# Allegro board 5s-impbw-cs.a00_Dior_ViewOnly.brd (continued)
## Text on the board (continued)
GND2: list("[Spacing] GND2" "Shape to Thru Via" "6 MIL [DEFAULT]" "5.99 MIL" "0.01 MIL" "DRC ERROR CLASS/GND2" "[ThruVia] USB3_TX_P2_OUT (VIA20D10A32) (9985.5 -6273.0)" "[Gnd2 Shape] GND ((9771.94 -9313.68) (17202.26 -5741.63))" list(9976.030000 -6269.780000) nil)@@@list("liquid_ni" "2014/02/18 09:27:21" nil "s0dcoa16607a" "5s-impbw-cs.104")@@@list("jake_ma" "2014/02/18 09:40:55" nil "s0dcoa89107" "5s-impbw-cs.104") | list("[Spacing] GND2" "Shape to Thru Via" "6 MIL [DEFAULT]" "5.99 MIL" "0.01 MIL" "DRC ERROR CLASS/GND2" "[ThruVia] USB3_RX_N3_OUT (VIA20D10A32) (9979.0 -6248.0)" "[Gnd2 Shape] GND ((9771.94 -9313.68) (17202.26 -5741.63))" list(9986.740000 -6254.330000) nil)@@@list("liquid_ni" "2014/02/18 09:27:20" nil "s0dcoa16607a" "5s-impbw-cs.104")@@@list("jake_ma" "2014/02/18 09:40:52" nil "s0dcoa89107" "5s-impbw-cs.104") | list("[Spacing] GND2" "Shape to Thru Via" "6 MIL [DEFAULT]" "5.99 MIL" "0.01 MIL" "DRC ERROR CLASS/GND2" "[ThruVia] USB3_TX_N2_OUT (TPCT30B20D10_SS16) (9995.0 -6302.5)" "[Gnd2 Shape] GND ((9771.94 -9313.68) (17202.26 -5741.63))" list(10004.520000 -6299.430000) nil)@@@list("liquid_ni" "2014/02/18 09:27:20" nil "s0dcoa16607a" "5s-impbw-cs.104")@@@list("jake_ma" "2014/02/18 09:40:53" nil "s0dcoa89107" "5s-impbw-cs.104") | list("[Spacing] GND2" "Shape to Thru Via" "6 MIL [DEFAULT]" "5.99 MIL" "0.01 MIL" "DRC ERROR CLASS/GND2" "[ThruVia] SATA_TXN1 (VIA20D10A32) (10481.51 -7037.77)" "[Gnd2 Shape] GND ((9771.94 -9313.68) (17202.26 -5741.63))" list(10490.660000 -7033.740000) nil)@@@list("liquid_ni" "2014/02/18 09:27:19" nil "s0dcoa16607a" "5s-impbw-cs.104")@@@list("jake_ma" "2014/02/18 09:40:50" nil "s0dcoa89107" "5s-impbw-cs.104") | list("[Spacing] GND2" "Shape to Thru Via" "6 MIL [DEFAULT]" "5.99 MIL" "0.01 MIL" "DRC ERROR CLASS/GND2" "[ThruVia] SATA_TXP0 (VIA20D10A32) (10510.6 -7038.2)" "[Gnd2 Shape] GND ((9771.94 -9313.68) (17202.26 -5741.63))" list(10501.450000 -7042.230000) nil)@@@list("liquid_ni" "2014/02/18 09:27:19" nil "s0dcoa16607a" "5s-impbw-cs.104")@@@list("jake_ma" "2014/02/18 09:40:51" nil "s0dcoa89107" "5s-impbw-cs.104") | list("[Spacing] GND2" "Thru Via to Thru Via" "5 MIL [(20)]" "4.24 MIL" "0.76 MIL" "DRC ERROR CLASS/GND2" "[ThruVia] SATA_TXP0 (VIA20D10A32) (10510.6 -7038.2)" "[ThruVia] SATA_TXN0 (VIA20D10A32) (10534.83 -7037.68)" list(10520.600000 -7037.990000) nil)@@@list("liquid_ni" "2014/02/18 09:27:24" nil "s0dcoa16607a" "5s-impbw-cs.104")@@@list("jake_ma" "2014/02/18 10:19:29" nil "S0DCOA89107" "5s-impbw-cs.104") | list("[Spacing] GND2" "1.Thru Via to Thru Via" "5 MIL [(20)]" "4.49 MIL" "0.51 MIL" "DRC ERROR CLASS/GND2" "[ThruVia] SATA_RXP0 (VIA20D10A32) (10722.16 -6789.07)" "[ThruVia] SATA_RXN0 (VIA20D10A32) (10746.63 -6790.03)" list(10732.150000 -6789.460000) nil)@@@list("liquid_ni" "2014/02/18 09:27:25" nil "s0dcoa16607a" "5s-impbw-cs.104")@@@list("jake_ma" "2014/02/18 10:27:57" nil "S0DCOA89107" "5s-impbw-cs.104") | list("[Spacing] GND2" "Shape to Route Keepout" "0 MIL [DEFAULT]" "0 MIL" "0.00 MIL" "DRC ERROR CLASS/GND2" "[Shape] Route Keepout/All ((12207.38 -8787.48) (12294.0 -8700.86))" "[Gnd2 Shape] GND ((9771.94 -9313.68) (17202.26 -5741.63))" list(12207.380000 -8744.170000) nil)@@@list("liquid_ni" "2014/02/18 09:27:21" nil "s0dcoa16607a" "5s-impbw-cs.104")@@@list("jake_ma" "2014/02/18 09:40:56" nil "s0dcoa89107" "5s-impbw-cs.104") | list("[Spacing] GND2" "Shape to Route Keepout" "0 MIL [DEFAULT]" "0 MIL" "0.00 MIL" "DRC ERROR CLASS/GND2" "[Shape] Route Keepout/All ((13694.97 -8866.99) (13781.59 -8780.37))" "[Gnd2 Shape] GND ((9771.94 -9313.68) (17202.26 -5741.63))" list(13781.590000 -8823.680000) nil)@@@list("liquid_ni" "2014/02/18 09:27:22" nil "s0dcoa16607a" "5s-impbw-cs.104")@@@list("jake_ma" "2014/02/18 09:40:58" nil "s0dcoa89107" "5s-impbw-cs.104") | list("[Spacing] GND2" "Shape to Route Keepout" "0 MIL [DEFAULT]" "0 MIL" "0.00 MIL" "DRC ERROR CLASS/GND2" "[Shape] Route Keepout/All ((16620.24 -7753.74) (16686.86 -7687.12))" "[Gnd2 Shape] GND ((9771.94 -9313.68) (17202.26 -5741.63))" list(16686.860000 -7720.430000) nil)@@@list("liquid_ni" "2014/02/18 09:27:22" nil "s0dcoa16607a" "5s-impbw-cs.104")@@@list("jake_ma" "2014/02/18 09:40:59" nil "s0dcoa89107" "5s-impbw-cs.104") | list("[Spacing] GND2" "Shape to Route Keepout" "0 MIL [DEFAULT]" "0 MIL" "0.00 MIL" "DRC ERROR CLASS/GND2" "[Shape] Route Keepout/All ((17114.81 -7812.93) (17207.43 -7720.31))" "[Gnd2 Shape] GND ((9771.94 -9313.68) (17202.26 -5741.63))" list(17115.610000 -7775.180000) nil)@@@list("liquid_ni" "2014/02/18 09:27:23" nil "s0dcoa16607a" "5s-impbw-cs.104")@@@list("jake_ma" "2014/02/18 09:41:00" nil "s0dcoa89107" "5s-impbw-cs.104") | list("[Spacing] GND2" "Shape to Route Keepout" "0 MIL [DEFAULT]" "0 MIL" "0.00 MIL" "DRC ERROR CLASS/GND2" "[Shape] Route Keepout/All ((17114.81 -6506.23) (17207.43 -6413.61))" "[Gnd2 Shape] GND ((9771.94 -9313.68) (17202.26 -5741.63))" list(17198.170000 -6432.140000) nil)@@@list("liquid_ni" "2014/02/18 09:27:23" nil "s0dcoa16607a" "5s-impbw-cs.104")@@@list("jake_ma" "2014/02/18 09:41:02" nil "s0dcoa89107" "5s-impbw-cs.104") | list("[Spacing] GND2" "Shape to Route Keepin" "0 MIL [DEFAULT]" "0 MIL" "0.00 MIL" "DRC ERROR CLASS/GND2" "[Shape] Route Keepin/All ((9771.94 -9313.68) (17202.26 -5741.63))" "[Gnd2 Shape] GND ((9771.94 -9313.68) (17202.26 -5741.63))" list(17202.260000 -6481.190000) nil)@@@list("liquid_ni" "2014/02/18 09:27:24" nil "s0dcoa16607a" "5s-impbw-cs.104")@@@list("jake_ma" "2014/02/18 09:41:03" nil "s0dcoa89107" "5s-impbw-cs.104")
User.28: R | E317539 | F2 | U13 | U14 | XDP1 | U4 | U3 | U2 | U5 | PU7 | 11 | 16 | 6 | 1 | U19 | 5 | U6 | U17 | 32 | 13 | 9 | UA3 | U16 | 48 | U21 | TEL:(02)81439001 FAX:(02)28973868 | TAIPEI | www.pegatroncorp.com | DESIGNED BY PEGATRON CORPORATION | DESIGNER: | DATE: | LAY#: | 2013.12.27/09:25:43 | 5S-IMPBW-CS.101 | JASON1_LIAO | CON5 | CON2 | F3J1 | ALL RIGHTS RESERVED | www.dell.com | COPYRIGHT 2013,12 | PCB MADE IN CHINA | REV:1.01 | R&D DEPARTMENT/ENGINEER: | PROJECT DESCRIPTION: | MODEL NAME: | IMPBW-CS | BU5/Stonko Chen | MAIN BOARD | REV. | 1.01 | SILKSCREEN | PRIMARY-SIDE | D33D66 | N14939 | 180 Degree
User.29: CON8 | CON1 | H6510 | SFIS | PU5 | 1 | 8 | U15 | CKX1 | 16 | H3 | H2 | H1 | X1 | H4 | U1 | X2 | U10 | 96 | 7 | 64 | 9 | 2 | 6 | 11 | PU6 | PU8 | 5 | 10 | 15 | X3 | PU3 | H9 | U20 | 12 | 36 | 24 | PU4 | 203 | 204 | 32 | P1 | S1 | TEL:(02)81439001 FAX:(02)28973868 | TAIPEI | www.pegatroncorp.com | DESIGNED BY PEGATRON CORPORATION | DESIGNER: | DATE: | LAY#: | 2013.12.27/09:25:43 | 5S-IMPBW-CS.101 | JASON1_LIAO | VCORE IC | CN1 | Touch control | CPU | DIMM1 | J1 | DC POGO PIN | E2 | M2 SSD | SPI ROM | EC | CON9 | HOME KEY | P2 | LVDS | M2 WLAN | RTC BATTERY | CON11 | CON4 | RIO | LIO | DC JACK IN | CON10 | FAN | CON7 | DIMM SLOT | FOR DDR3L ONLY | CONSATA | BATTERY | CAMERA | CON6 | CONWIFI | SATA HDD | CON3 | R&D DEPARTMENT/ENGINEER: | PROJECT DESCRIPTION: | MODEL NAME: | IMPBW-CS | BU5/Stonko Chen | MAIN BOARD | REV. | 1.01 | SILKSCREEN | SECONDARY-SIDE
User.37: FIGURE | SIZE | 10.0 | 12.0 | 18.0 | 28.0 | 30.0 | 47.0 | 83.0 | 130.0 | 43.0 | 59.0 | 63.0 | 69.0 | 87.0 | 118.0 | 125.0 | 160.0 | 82.0x39.0 | 102.0x83.0 | TOLERANCE | +3.0/-3.0 | +2.0/-2.0 | DRILL CHART: TOP to BOTTOM (1 to 8) | ALL UNITS ARE IN MILS | PLATED | NON-PLATED | ROTATION | - | 0.000 | 90.000 | QTY | 3744 | 47 | 220 | 22 | 4 | 5 | 1 | 2 | 3 | 4072 | TOTAL HOLES:
